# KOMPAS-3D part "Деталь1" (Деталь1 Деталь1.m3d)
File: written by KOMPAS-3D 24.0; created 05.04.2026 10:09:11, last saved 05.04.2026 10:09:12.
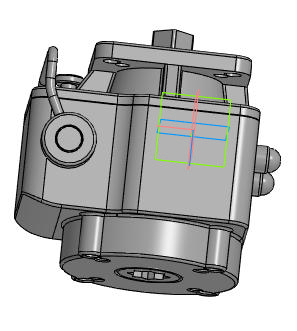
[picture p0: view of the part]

Document properties: Автор: R2D2; Полное имя файла: E:\Работа\Зайцев\Аксессуары для пневмоприводов\Ручной дублер DN.ru\MON3-700-T38-ISO Ручной дублер DN.ru\исходные материалы\Деталь1 Деталь1.m3d

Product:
- Part/product: Деталь1
    Масса: 21.052029
    additional columns: Типовые

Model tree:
1. Операция без истории:1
